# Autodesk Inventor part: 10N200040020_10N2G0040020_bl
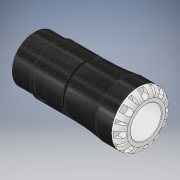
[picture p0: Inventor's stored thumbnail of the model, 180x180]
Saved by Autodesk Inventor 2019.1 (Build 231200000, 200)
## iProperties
Created: 2016-12
Part Number: 10N200040020_10N2G0040020_bl
Material: PVC-Piping
Description: PLASSON MALE ADAPTOR 40X2" SERIES 1
Document SubType Name: Modeling
Designer: KIM
Mass: 61.7504 g
Surface Area: 140.097 cm^2
Volume: 44.1074 cm^3
Density: 1.4 g/cm^3
Appearance: Black Cast
Author: KIM
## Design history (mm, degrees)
derived "10N20.ipt"
feature "Solid1::10N20.ipt" dims "ScaleForDerivedMember" = 10
tag "TaggingFeature1"
body "Solid1"
other parameters: "d0" = 146 [user parameter], "d1" = 30.66 [user parameter], "d6" = 73 [user parameter], "d8" = 63 [user parameter], "d13" = 8 [user parameter], "d14" = 8 [user parameter], "d15" = 0 [user parameter], "d17" = 360 deg [user parameter], "d19" = 8 deg [user parameter], "d20" = 0.8 [user parameter], "d21" = 0.8 [user parameter], "d22" = 8 deg [user parameter], "d24" = 0 [user parameter], "d26" = 360 deg [user parameter], "d32" = 0.925 [user parameter], "d33" = 7 [user parameter], "d34" = 59.614 [user parameter], "d35" = 5 [user parameter], "d38" = 26 [user parameter], "d39" = 1.78842 [user parameter], "d42" = 14 [user parameter], "d43" = 9.2 [user parameter], "d45" = 15.68 [user parameter], "d46" = 0 [user parameter], "d59" = 360 deg [user parameter], "d61" = 11.9 [user parameter], "d62" = 0.8 [user parameter], "d64" = 0 [user parameter], "d65" = 0.7 [user parameter], "d69" = 2 [user parameter], "d70" = 2.19 [user parameter], "d71" = 3 [user parameter], "d73" = 1 [user parameter], "H_" = 146 [user parameter], "l_" = 73 [user parameter], "R_" = 59.614 [user parameter], "l_2" = 26 [user parameter]
